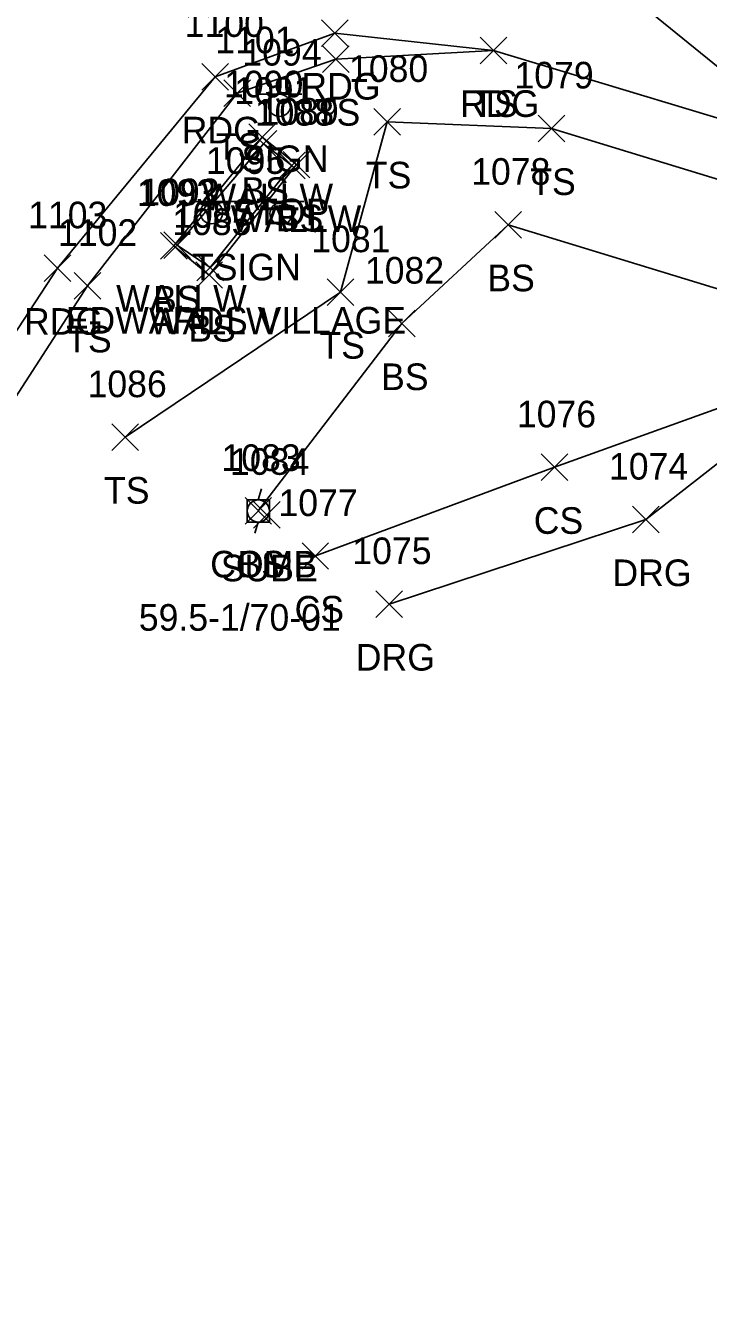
# Model space of a CAD drawing. Extents: x 1537342 to 1542195, y 163002 to 168596.
# Drawn here: x 1541992.5 to 1542043.7, y 163030.1 to 163127.1 of the extents above; entities that cross this region are included whole.
import ezdxf

# ---------------------------------------------------------------- set-up
doc = ezdxf.new("R2010")
doc.units = 0
for name, color, linetype in [('L_A', 7, 'Continuous'), ('L_I', 7, 'Continuous'), ('L_TIC', 7, 'Continuous'), ('LELB', 7, 'Continuous'), ('LW', 7, 'Continuous'), ('P_A', 7, 'Continuous'), ('P_I', 7, 'Continuous'), ('P_TIC', 7, 'Continuous'), ('PET', 7, 'Continuous'), ('PEU', 7, 'Continuous'), ('R_A', 7, 'Continuous'), ('R_I', 7, 'Continuous'), ('R_TIC', 7, 'Continuous'), ('RDG', 7, 'Continuous'), ('S_A', 7, 'Continuous'), ('S_C', 7, 'Continuous'), ('S_I', 7, 'Continuous'), ('SSGN', 7, 'Continuous'), ('U_A', 7, 'Continuous'), ('U_C', 7, 'Continuous'), ('U_I', 7, 'Continuous'), ('U_TIC', 7, 'Continuous'), ('UP', 7, 'Continuous')]:
    doc.layers.add(name, color=color, linetype=linetype)

msp = doc.modelspace()

# ---------------------------------------------------------------- linework, layer by layer
at = {"layer": 'L_TIC'}
for points in [[(1542026.612, 163124.215), (1542028.612, 163126.215)], [(1542028.612, 163124.215), (1542026.612, 163126.215)], [(1542014.775, 163123.561), (1542016.775, 163125.561)], [(1542016.775, 163123.561), (1542014.775, 163125.561)], [(1542007.354, 163120.994), (1542009.354, 163122.994)], [(1542009.354, 163120.994), (1542007.354, 163122.994)], [(1542018.614, 163118.843), (1542020.614, 163120.843)], [(1542020.614, 163118.843), (1542018.614, 163120.843)], [(1542009.231, 163117.685), (1542011.231, 163119.685)], [(1542011.231, 163117.685), (1542009.231, 163119.685)], [(1542030.961, 163118.353), (1542032.961, 163120.353)], [(1542032.961, 163118.353), (1542030.961, 163120.353)], [(1542009.335, 163117.197), (1542011.335, 163119.197)], [(1542011.335, 163117.197), (1542009.335, 163119.197)], [(1542011.454, 163115.563), (1542013.454, 163117.563)], [(1542013.454, 163115.563), (1542011.454, 163117.563)], [(1542011.816, 163115.63), (1542013.816, 163117.63)], [(1542013.816, 163115.63), (1542011.816, 163117.63)], [(1542027.703, 163111.118), (1542029.703, 163113.118)], [(1542029.703, 163111.118), (1542027.703, 163113.118)], [(1542002.594, 163109.527), (1542004.594, 163111.527)], [(1542004.594, 163109.527), (1542002.594, 163111.527)], [(1542002.594, 163109.527), (1542004.594, 163111.527)], [(1542004.594, 163109.527), (1542002.594, 163111.527)], [(1542002.852, 163109.583), (1542004.852, 163111.583)], [(1542004.852, 163109.583), (1542002.852, 163111.583)], [(1542002.852, 163109.583), (1542004.852, 163111.583)], [(1542004.852, 163109.583), (1542002.852, 163111.583)], [(1542005.317, 163107.892), (1542007.317, 163109.892)], [(1542007.317, 163107.892), (1542005.317, 163109.892)], [(1542005.317, 163107.892), (1542007.317, 163109.892)], [(1542007.317, 163107.892), (1542005.317, 163109.892)], [(1542005.248, 163107.34), (1542007.248, 163109.34)], [(1542007.248, 163107.34), (1542005.248, 163109.34)], [(1542005.248, 163107.34), (1542007.248, 163109.34)], [(1542007.248, 163107.34), (1542005.248, 163109.34)], [(1541996.105, 163106.527), (1541998.105, 163108.527)], [(1541998.105, 163106.527), (1541996.105, 163108.527)], [(1542015.125, 163106.056), (1542017.125, 163108.056)], [(1542017.125, 163106.056), (1542015.125, 163108.056)], [(1542019.721, 163103.695), (1542021.721, 163105.695)], [(1542021.721, 163103.695), (1542019.721, 163105.695)], [(1541998.946, 163095.163), (1542000.946, 163097.163)], [(1542000.946, 163095.163), (1541998.946, 163097.163)], [(1542031.191, 163092.896), (1542033.191, 163094.896)], [(1542033.191, 163092.896), (1542031.191, 163094.896)], [(1542008.944, 163089.618), (1542010.944, 163091.618)], [(1542010.944, 163089.618), (1542008.944, 163091.618)], [(1542013.227, 163086.232), (1542015.227, 163088.232)], [(1542015.227, 163086.232), (1542013.227, 163088.232)]]:
    msp.add_lwpolyline(points, dxfattribs=at)
at = {"layer": 'LELB'}
for points in [[(1542027.612, 163125.215), (1542015.775, 163124.561), (1542008.354, 163121.994), (1541997.105, 163107.527), (1541982.887, 163085.546)], [(1542057.246, 163109.096), (1542051.535, 163113.36), (1542031.961, 163119.353), (1542019.614, 163119.843), (1542016.125, 163107.056), (1541999.946, 163096.163)], [(1542006.248, 163108.34), (1542012.816, 163116.63), (1542010.231, 163118.685), (1542003.594, 163110.527)], [(1542051.535, 163113.36), (1542046.804, 163106.574), (1542050.946, 163101.753), (1542054.254, 163101.848), (1542032.191, 163093.896), (1542014.227, 163087.232)], [(1542053.2, 163109.678), (1542055.238, 163106.234), (1542054.141, 163104.992), (1542049.99, 163106.268), (1542046.804, 163106.574), (1542028.703, 163112.118), (1542020.721, 163104.695), (1542009.944, 163090.618)], [(1542006.248, 163108.34), (1542003.594, 163110.527)]]:
    msp.add_lwpolyline(points, dxfattribs=at)
at = {"layer": 'LW'}
for points in [[(1542006.317, 163108.892), (1542012.454, 163116.563), (1542010.335, 163118.197), (1542003.852, 163110.583)], [(1542006.317, 163108.892), (1542003.852, 163110.583)]]:
    msp.add_lwpolyline(points, dxfattribs=at)
at = {"layer": 'P_TIC'}
for points in [[(1542014.691, 163125.518), (1542016.691, 163127.518)], [(1542016.691, 163125.518), (1542014.691, 163127.518)], [(1542026.612, 163124.215), (1542028.612, 163126.215)], [(1542028.612, 163124.215), (1542026.612, 163126.215)], [(1542005.704, 163122.225), (1542007.704, 163124.225)], [(1542007.704, 163122.225), (1542005.704, 163124.225)], [(1541993.858, 163107.85), (1541995.858, 163109.85)], [(1541995.858, 163107.85), (1541993.858, 163109.85)]]:
    msp.add_lwpolyline(points, dxfattribs=at)
at = {"layer": 'PET'}
msp.add_lwpolyline([(1542165.564, 163030.05), (1542126.673, 163058.359), (1542096.316, 163082.469), (1542058.609, 163112.541), (1542052.024, 163117.841), (1542010.734, 163151.352), (1541978.729, 163177.477), (1541958.58, 163193.326), (1541928.576, 163217.895), (1541894.651, 163244.61), (1541857.529, 163271.038), (1541839.599, 163283.446), (1541795.579, 163311.161), (1541814.195, 163318.824), (1541832.215, 163326.687)], dxfattribs=at)
at = {"layer": 'PEU'}
msp.add_lwpolyline([(1542052.024, 163117.841), (1542027.612, 163125.215), (1542015.691, 163126.518), (1542006.704, 163123.225), (1541994.858, 163108.85), (1541980.147, 163086.379)], dxfattribs=at)
at = {"layer": 'R_TIC'}
for points in [[(1542038.053, 163088.97), (1542040.053, 163090.97)], [(1542040.053, 163088.97), (1542038.053, 163090.97)], [(1542018.776, 163082.622), (1542020.776, 163084.622)], [(1542020.776, 163082.622), (1542018.776, 163084.622)]]:
    msp.add_lwpolyline(points, dxfattribs=at)
at = {"layer": 'RDG'}
msp.add_lwpolyline([(1542058.609, 163112.541), (1542057.246, 163109.096), (1542054.254, 163101.848), (1542039.053, 163089.97), (1542019.776, 163083.622)], dxfattribs=at)
at = {"layer": 'SSGN'}
for p, q in [((1542009.888, 163121.924), (1542013.221, 163121.924)), ((1542011.535, 163121.091), (1542011.535, 163121.091)), ((1542004.766, 163113.857), (1542013.363, 163113.857)), ((1542008.788, 163112.953), (1542008.788, 163112.953))]:
    msp.add_line(p, q, dxfattribs=at)
for centre in [(1542011.535, 163121.091), (1542006.427, 163113.024), (1542011.642, 163112.954)]:
    msp.add_circle(centre, 0.833, dxfattribs=at)
at = {"layer": 'U_TIC'}
for points in [[(1542009.589, 163089.329), (1542011.589, 163091.329)], [(1542011.589, 163089.329), (1542009.589, 163091.329)]]:
    msp.add_lwpolyline(points, dxfattribs=at)
at = {"layer": 'UP'}
for p, q in [((1542010.194, 163092.285), (1542009.944, 163091.452)), ((1542009.11, 163089.785), (1542009.11, 163091.452)), ((1542009.11, 163091.452), (1542010.777, 163091.452)), ((1542010.777, 163091.452), (1542010.777, 163089.785)), ((1542009.944, 163090.618), (1542009.944, 163090.618)), ((1542010.777, 163089.785), (1542009.11, 163089.785)), ((1542009.694, 163088.952), (1542009.944, 163089.785))]:
    msp.add_line(p, q, dxfattribs=at)
msp.add_circle((1542009.944, 163090.618), 0.833, dxfattribs=at)

# ---------------------------------------------------------------- texts
at = {"layer": 'L_A'}
for s, p in [('TS', (1542014.184, 163119.561)), ('TS', (1542026.022, 163120.215)), ('TS', (1542006.764, 163116.994)), ('TS', (1542018.024, 163114.843)), ('BS', (1542008.672, 163113.685)), ('TS', (1542030.371, 163114.353)), ('WALLW', (1542005.752, 163113.197)), ('BS', (1542011.257, 163111.63)), ('WALLW', (1542007.871, 163111.563)), ('BS', (1542027.144, 163107.118)), ('WALLW', (1541999.269, 163105.583)), ('WALLW', (1541999.269, 163105.583)), ('BS', (1542002.035, 163105.527)), ('BS', (1542002.035, 163105.527)), ('WALLW', (1542001.734, 163103.892)), ('WALLW', (1542001.734, 163103.892)), ('BS', (1542004.689, 163103.34)), ('BS', (1542004.689, 163103.34)), ('TS', (1541995.514, 163102.527)), ('TS', (1542014.535, 163102.056)), ('BS', (1542019.162, 163099.695)), ('TS', (1541998.355, 163091.163)), ('CS', (1542030.632, 163088.896)), ('BS', (1542008.385, 163085.618)), ('CS', (1542012.668, 163082.232))]:
    msp.add_text(s, height=2, dxfattribs=at).set_placement(p)
at = {"layer": 'L_I'}
for s, p in [('1101', (1542006.717, 163124.994)), ('1080', (1542016.756, 163122.843)), ('1079', (1542029.182, 163122.353)), ('1090', (1542007.373, 163121.685)), ('1091', (1542008.13, 163121.197)), ('1088', (1542009.682, 163119.563)), ('1089', (1542010.037, 163119.63)), ('1078', (1542025.931, 163115.118)), ('1093', (1542000.822, 163113.527)), ('1093', (1542000.822, 163113.527)), ('1092', (1542001.081, 163113.583)), ('1092', (1542001.081, 163113.583)), ('1087', (1542003.545, 163111.892)), ('1087', (1542003.545, 163111.892)), ('1085', (1542003.476, 163111.34)), ('1085', (1542003.476, 163111.34)), ('1102', (1541994.9, 163110.527)), ('1081', (1542013.921, 163110.056)), ('1082', (1542017.949, 163107.695)), ('1086', (1541997.119, 163099.163)), ('1076', (1542029.364, 163096.896)), ('1083', (1542007.172, 163093.618)), ('1077', (1542011.456, 163090.232))]:
    msp.add_text(s, height=2, dxfattribs=at).set_placement(p)
at = {"layer": 'P_A'}
for p in [(1542013.179, 163121.518), (1542025.1, 163120.215), (1542004.192, 163118.225), (1541992.346, 163103.85)]:
    msp.add_text('RDG', height=2, dxfattribs=at).set_placement(p)
at = {"layer": 'P_I'}
for s, p in [('1100', (1542004.413, 163126.225)), ('1103', (1541992.653, 163111.85))]:
    msp.add_text(s, height=2, dxfattribs=at).set_placement(p)
at = {"layer": 'R_A'}
for p in [(1542036.541, 163084.97), (1542017.264, 163078.622)]:
    msp.add_text('DRG', height=2, dxfattribs=at).set_placement(p)
at = {"layer": 'R_I'}
for s, p in [('1074', (1542036.282, 163092.97)), ('1075', (1542017.005, 163086.622))]:
    msp.add_text(s, height=2, dxfattribs=at).set_placement(p)
at = {"layer": 'S_A'}
for s, p in [('SIGN', (1542008.673, 163116.071)), ('TSIGN', (1542004.964, 163107.936))]:
    msp.add_text(s, height=2, dxfattribs=at).set_placement(p)
at = {"layer": 'S_C'}
for s, p in [('STOP', (1542007.996, 163112.071)), ('EDWARDS VILLAGE', (1541995.476, 163103.936))]:
    msp.add_text(s, height=2, dxfattribs=at).set_placement(p)
at = {"layer": 'S_I'}
for s, p in [('1094', (1542008.744, 163124.071)), ('1095', (1542006.011, 163115.936))]:
    msp.add_text(s, height=2, dxfattribs=at).set_placement(p)
at = {"layer": 'U_A'}
for s, p in [('COMB', (1542006.329, 163085.618)), ('SUBE', (1542007.124, 163085.329))]:
    msp.add_text(s, height=2, dxfattribs=at).set_placement(p)
at = {"layer": 'U_C'}
msp.add_text('59.5-1/70-01', height=2, dxfattribs=at).set_placement((1542000.967, 163081.618))
at = {"layer": 'U_I'}
for s, p in [('1083', (1542007.172, 163093.618)), ('1084', (1542007.817, 163093.329))]:
    msp.add_text(s, height=2, dxfattribs=at).set_placement(p)

doc.saveas('drawing.dxf')
